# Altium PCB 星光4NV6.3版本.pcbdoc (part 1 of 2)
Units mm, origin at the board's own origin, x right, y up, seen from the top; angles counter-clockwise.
Board outline 96.4 x 47 mm, 2 copper layers (Top Layer, Bottom Layer), stack 1.58 mm thick; 27 components, 21 nets, 136 pads, 174 vias.
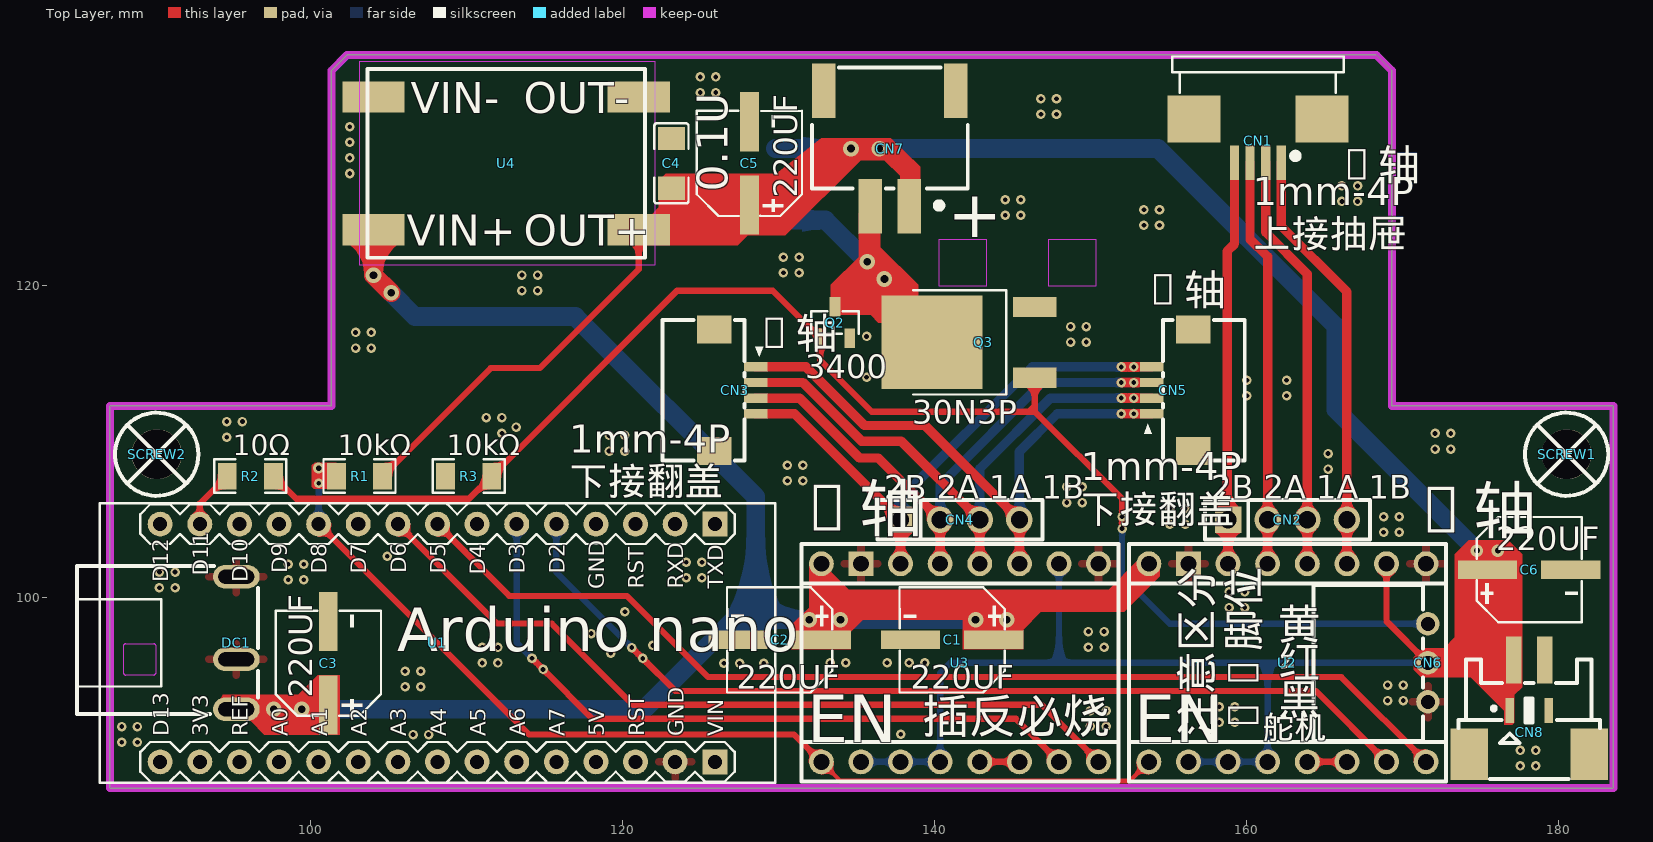
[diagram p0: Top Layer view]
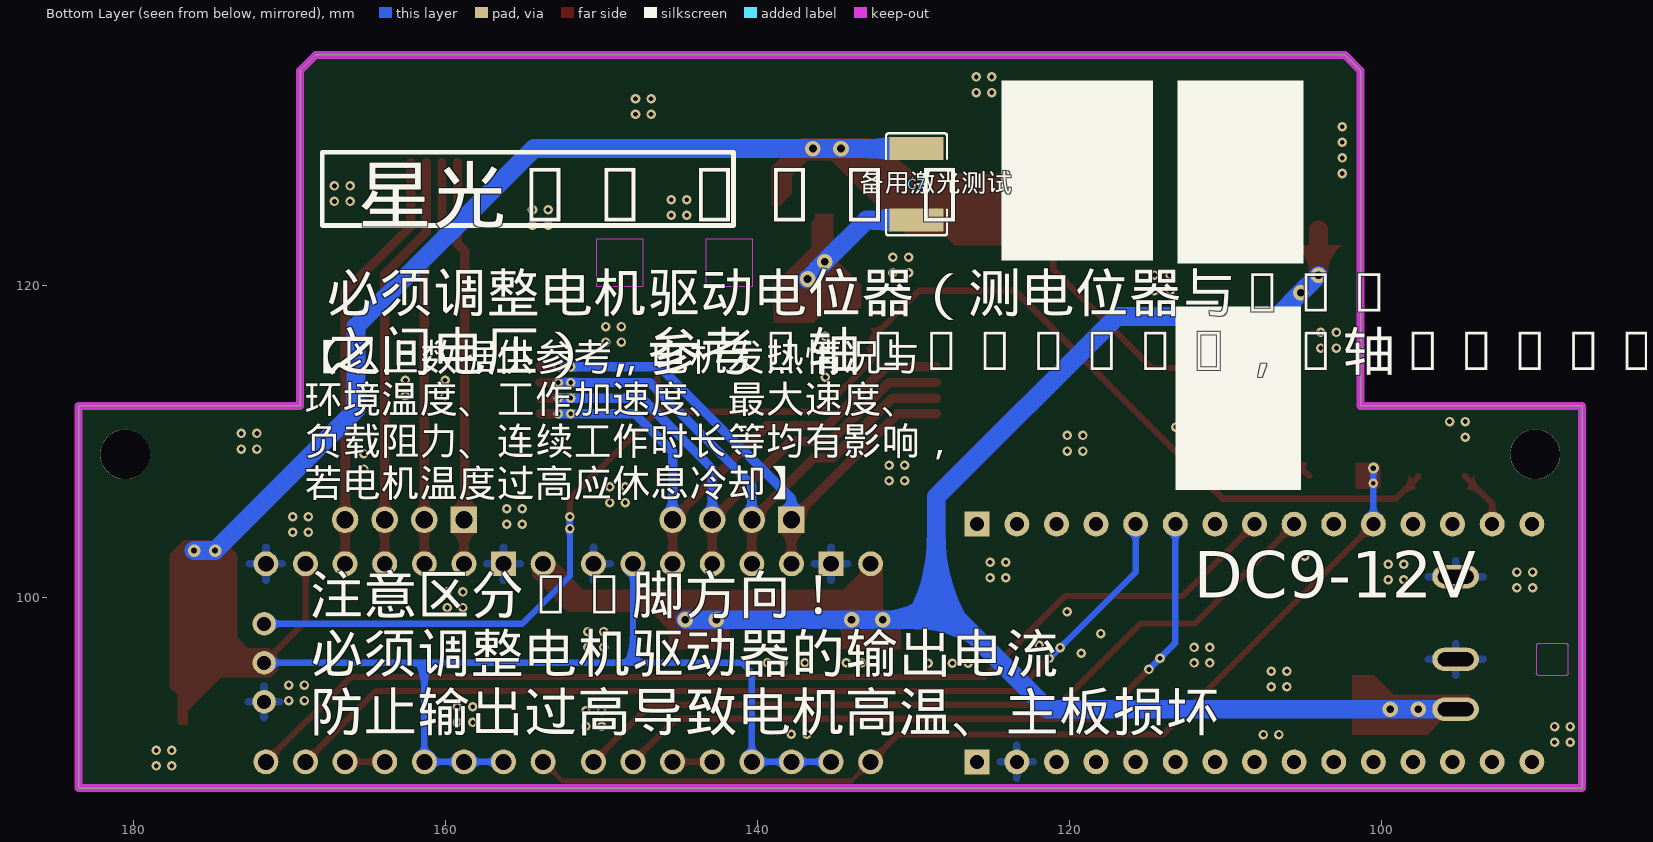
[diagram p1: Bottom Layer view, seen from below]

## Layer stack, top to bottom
Top Solder Mask Layer: solder mask 0.01, Dk 3.3
Top Layer: signal copper 0.035
Dielectric1: surface 1.51, FR4, Dk 4.5
Bottom Layer: signal copper 0.035
Bottom Solder Mask Layer: solder mask 0.01, Dk 3.3

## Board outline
102.322,134.757 168.322,134.757 169.322,133.757 169.322,112.257 169.322,119.257 169.322,112.257 183.522,112.257 183.522,87.757 87.122,87.757 87.122,112.257 101.322,112.257 101.322,133.757

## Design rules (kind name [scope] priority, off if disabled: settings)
BoardOutlineClearance copperThickness1oz [All] p0: genericclearance=0.254 ignorepadtopadclearanceinfootprint=FALSE except(0: Arc-SplitContinuation Track-SplitContinuation SMDPad-SplitContinuation THPad-SplitContinuation Via-SplitContinuation Fill-SplitContinuation Poly-SplitContinuation Region-SplitContinuation Text-SplitContinuation)
BoardOutlineClearance copperThickness2oz [All] p0: genericclearance=0.254 ignorepadtopadclearanceinfootprint=FALSE except(0: Arc-SplitContinuation Track-SplitContinuation SMDPad-SplitContinuation THPad-SplitContinuation Via-SplitContinuation Fill-SplitContinuation Poly-SplitContinuation Region-SplitContinuation Text-SplitContinuation)
BoardOutlineClearance Plane_innerPlane [All] p0: genericclearance=0.254 ignorepadtopadclearanceinfootprint=FALSE except(0: Arc-SplitContinuation Track-SplitContinuation SMDPad-SplitContinuation THPad-SplitContinuation Via-SplitContinuation Fill-SplitContinuation Poly-SplitContinuation Region-SplitContinuation Text-SplitContinuation)
BoardOutlineClearance Copper_copperRegion [All] p0: genericclearance=0.254 ignorepadtopadclearanceinfootprint=FALSE except(0: Arc-SplitContinuation Track-SplitContinuation SMDPad-SplitContinuation THPad-SplitContinuation Via-SplitContinuation Fill-SplitContinuation Poly-SplitContinuation Region-SplitContinuation Text-SplitContinuation)
BoardOutlineClearance Copper_copperRegion1 [All] p0: genericclearance=0.254 ignorepadtopadclearanceinfootprint=FALSE except(0: Arc-SplitContinuation Track-SplitContinuation SMDPad-SplitContinuation THPad-SplitContinuation Via-SplitContinuation Fill-SplitContinuation Poly-SplitContinuation Region-SplitContinuation Text-SplitContinuation)
BoardOutlineClearance otherClearance [All] p0: genericclearance=0.254 ignorepadtopadclearanceinfootprint=FALSE except(0: Arc-SplitContinuation Track-SplitContinuation SMDPad-SplitContinuation THPad-SplitContinuation Via-SplitContinuation Fill-SplitContinuation Poly-SplitContinuation Region-SplitContinuation Text-SplitContinuation)
Clearance copperThickness1oz [All] p1: gap=0.178 ignorepadtopadclearanceinfootprint=FALSE
Clearance copperThickness2oz [All] p1: gap=0.178 ignorepadtopadclearanceinfootprint=FALSE
Clearance Plane_innerPlane [All] p1: gap=0.178 ignorepadtopadclearanceinfootprint=FALSE
Clearance Copper_copperRegion [All] p1: gap=0.178 ignorepadtopadclearanceinfootprint=FALSE
Clearance Copper_copperRegion1 [All] p1: gap=0.178 ignorepadtopadclearanceinfootprint=FALSE
Clearance otherClearance [All] p1: gap=0.178 ignorepadtopadclearanceinfootprint=FALSE
DiffPairsRouting differentialPair [All] p1: maxuncoupledlength=10 minlimit=5.9843 maxlimit=Infinity mostfreqgap=5.9843 toplayer_minwidth=5 toplayer_prefwidth=10 toplayer_maxwidth=100 bottomlayer_minwidth=5 bottomlayer_prefwidth=10 bottomlayer_maxwidth=100
PasteMaskExpansion pasteMaskExpansion [All] p1: expansion=0
PlaneConnect innerPlane [All] p1: planeconnectstyle=Relief reliefexpansion=0.508 reliefentries=4 reliefconductorwidth=0.254 reliefairgap=0.254
PolygonConnect copperRegion [All] p1: connectstyle=Relief reliefentries=4 reliefconductorwidth=10 polygonreliefangle="90 Angle" airgapwidth=10
PolygonConnect copperRegion1 [All] p1: connectstyle=Relief reliefentries=4 reliefconductorwidth=19.685 polygonreliefangle="90 Angle" airgapwidth=10
RoutingVias viaSize [All] p1: viastyle="Through Hole" holewidth=12.0078 minholewidth=11.811 maxholewidth=248.0314 width=12.0078 minwidth=11.811 maxwidth=248.0314
SolderMaskExpansion solderMaskExpansion [All] p1: useseparateexpansions=TRUE expansion=2.0079 expansionbottom=2.0079
Width copperThickness1oz [All] p1: maxlimit=100 minlimit=5 preferedwidth=20
Width copperThickness2oz [All] p1: maxlimit=100 minlimit=5 preferedwidth=10

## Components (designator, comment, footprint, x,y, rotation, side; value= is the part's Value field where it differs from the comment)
C1 "" CAP-SMD_BD6.3-L6.6-W6.6-FD-1 141.122,97.257 r180 top
C2 "" CAP-SMD_BD6.3-L6.6-W6.6-FD-1 130.062,97.257 r180 top
C3 "" CAP-SMD_BD6.3-L6.6-W6.6-FD-1 101.122,95.757 r90 top
C4 "100nF" C1206 123.122,127.807 r270 top
C5 "" CAP-SMD_BD6.3-L6.6-W6.6-FD-1 128.122,127.807 r90 top
C6 "" CAP-SMD_BD6.3-L6.6-W6.6-FD-1 178.122,101.757 r0 top
C7 "" C1812 129.794,126.464 r90 bottom
CN1 "" FPC-SMD_4P-P1.00_AFA07-S04ECC-00 160.722,129.257 r180 top
CN2 "" HDR-TH_4P-P2.54-V-F 162.622,104.957 r0 top
CN3 "" FPC-SMD_4P-P1.00_10A20L04P 127.122,113.257 r270 top
CN4 "" HDR-TH_4P-P2.54-V-F 141.622,104.957 r0 top
CN5 "" FPC-SMD_4P-P1.00_10A20L04P 155.322,113.257 r90 top
CN6 "" HDR-TH_3P-P2.50_ZX-XH2.54-3PWZ 171.622,95.787 r270 top
CN7 "" CONN-SMD_2P-P2.54_MEGASTAR_ZX-XH2.54-2PWT 137.122,128.757 r180 top
CN8 "" CONN-SMD_1.25-3P 178.122,91.257 r0 top
DC1 "" DC-IN-TH_DC044 95.222,97.057 r0 top
Q2 "" SOT-23-3_L2.9-W1.3-P1.90-LS2.4-BR 133.604,117.602 r270 top
Q3 "" TO-252-2_L6.6-W6.1-P4.57-LS9.9-TL-CW 143.122,116.332 r180 top
R1 "10kΩ" R1206 103.122,107.757 r0 top
R2 "10Ω" R1206 96.122,107.757 r180 top
R3 "10kΩ" R1206 110.122,107.757 r0 top
SCREW1 "" M3螺丝 180.522,109.157 r0 top
SCREW2 "" M3螺丝 90.122,109.157 r0 top
U1 "" COMM-TH_ARDUINO_NANO 108.122,97.057 r0 top
U2 "" DIP-16_L20.3-W15.2-P2.54_LS12.7_A4988 162.622,95.787 r90 top
U3 "" DIP-16_L20.3-W15.2-P2.54_LS12.7_A4988 141.622,95.787 r90 top
U4 "" 迷你稳压模块 103.622,121.757 r0 top

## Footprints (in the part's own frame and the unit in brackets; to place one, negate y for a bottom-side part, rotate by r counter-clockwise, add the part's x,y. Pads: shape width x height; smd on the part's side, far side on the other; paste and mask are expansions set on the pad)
C1206 [mm]
  rect 1.485x1.728 smd: 1(-1.593,0) 2(1.593,0)
  silkscreen extent -2.56,-1.09 2.56,1.09
C1812 [mm]
  rect 1.485x3.456 smd: 1(-2.293,0) 2(2.293,0)
  silkscreen extent -3.26,-1.96 3.26,1.96
CAP-SMD_BD6.3-L6.6-W6.6-FD-1 [mm]
  rect 3.8x1.2 smd: 1(-2.67,0) 2(2.67,0)
  silkscreen extent -3.38,-3.38 3.38,3.38
COMM-TH_ARDUINO_NANO [mm]
  rect 1.6x1.6 hole 0.9: 1(17.78,7.62) 30(17.78,-7.62)
  round 1.6 hole 0.9: 2(15.24,7.62) 4(10.16,7.62) 6(5.08,7.62) 8(0,7.62) 10(-5.08,7.62) 12(-10.16,7.62) 14(-15.24,7.62) 15(-17.78,7.62) 16(-17.78,-7.62) 18(-12.7,-7.62) 20(-7.62,-7.62) 22(-2.54,-7.62) 24(2.54,-7.62) 26(7.62,-7.62) 28(12.7,-7.62) 29(15.24,-7.62)
  round 1.6 hole 0.9 copper offset 0,0: 3(12.7,7.62)
  round 1.6 hole 0.9 copper offset -0.001,0: 5(7.621,7.62) 7(2.541,7.62) 9(-2.539,7.62) 11(-7.619,7.62) 13(-12.699,7.62)
  round 1.6 hole 0.9 copper offset 0.001,0: 17(-15.241,-7.62) 19(-10.161,-7.62) 21(-5.081,-7.62) 23(-0.001,-7.62) 25(5.079,-7.62) 27(10.159,-7.62)
  silkscreen extent -23.11,-8.97 21.67,8.97
CONN-SMD_1.25-3P [mm]
  rect 0.52x1.6 smd: 1(-1.25,1.475) 3(1.25,1.475)
  rect 2.4x3.3 smd: 4(3.85,-1.325) 5(-3.85,-1.325)
  silkscreen extent -4.52,-2.92 4.53,2.24
CONN-SMD_2P-P2.54_MEGASTAR_ZX-XH2.54-2PWT [mm]
  rect 1.5x3.5 smd: 1(-1.25,3.7) 2(1.25,3.7) 3(-4.23,-3.7) 4(4.23,-3.7)
  silkscreen extent -5,-5.21 5,3.85
DC-IN-TH_DC044 [mm]
  oval 3x1.5 hole 0.9 slot 2.3 at 0 deg: 2(0,4.25) 3(0,-1.05) 4(0,-4.25)
  Board Outline Layer lines w0.003: -7.209,-1.939 -7.209,-0.161 cw(c-7.082,-0.161) -7.082,-0.034 -5.304,-0.034 cw(c-5.304,-0.161) -5.177,-0.161 -5.177,-1.939 cw(c-5.304,-1.939) -5.304,-2.066 -7.082,-2.066 cw(c-7.082,-1.939) -7.209,-1.939
  Board Outline Layer region: -7.209,-1.939 -7.209,-0.161 -7.199,-0.112 -7.172,-0.071 -7.131,-0.044 -7.082,-0.034 -7.082,-0.034 -5.304,-0.034 -5.255,-0.044 -5.214,-0.071 -5.187,-0.112 -5.177,-0.161 -5.177,-0.161 -5.177,-1.939 -5.187,-1.988 -5.214,-2.029 -5.255,-2.056 -5.304,-2.066 -5.304,-2.066 -7.082,-2.066 -7.131,-2.056 -7.172,-2.029 -7.199,-1.988 -7.209,-1.939
  Board Outline Layer region: -7.209,-1.939 -7.209,-0.161 -7.199,-0.112 -7.172,-0.071 -7.131,-0.044 -7.082,-0.034 -7.082,-0.034 -5.304,-0.034 -5.255,-0.044 -5.214,-0.071 -5.187,-0.112 -5.177,-0.161 -5.177,-0.161 -5.177,-1.939 -5.187,-1.988 -5.214,-2.029 -5.255,-2.056 -5.304,-2.066 -5.304,-2.066 -7.082,-2.066 -7.131,-2.056 -7.172,-2.029 -7.199,-1.988 -7.209,-1.939
  silkscreen extent -10.2,-4.55 1.4,4.95
DIP-16_L20.3-W15.2-P2.54_LS12.7_A4988 [mm]
  round 1.6 hole 1.02: 1(-6.35,8.89) 2(-6.35,6.35) 3(-6.35,3.81) 4(-6.35,1.27) 5(-6.35,-1.27) 6(-6.35,-3.81) 7(-6.35,-6.35) 8(-6.35,-8.89) 9(6.35,-8.89) 10(6.35,-6.35) 11(6.35,-3.81) 12(6.35,-1.27) 13(6.35,1.27) 14(6.35,3.81) 16(6.35,8.89)
  rect 1.6x1.6 hole 1.02: 15(6.35,6.35)
  silkscreen extent -7.62,-10.16 7.62,10.16
FPC-SMD_4P-P1.00_10A20L04P [mm]
  rect 0.6x1.5 smd: 1(-1.5,1.4) 2(-0.5,1.4) 3(0.5,1.4) 4(1.5,1.4)
  rect 1.8x2.2 smd: 5(3.9,-1.263) 6(-3.9,-1.263)
  silkscreen extent -4.5,-4.56 4.5,1.9
FPC-SMD_4P-P1.00_AFA07-S04ECC-00 [mm]
  rect 0.6x2.2 smd: 1(-1.5,1.4) 2(-0.5,1.4) 3(0.5,1.4) 4(1.5,1.4)
  rect 3.4x3 smd: 5(4.1,-1.4) 6(-4.1,-1.4)
  silkscreen extent -5.5,-5.4 5.5,1.17
HDR-TH_3P-P2.50_ZX-XH2.54-3PWZ [mm]
  round 1.5 hole 0.9: 1(-2.5,0) 2(0,0) 3(2.5,0)
  silkscreen extent -5,-7.32 5,-0.32
HDR-TH_4P-P2.54-V-F [mm]
  rect 1.7x1.7 hole 1.1: 1(-3.81,0)
  round 1.7 hole 1.1: 2(-1.27,0) 3(1.27,0) 4(3.81,0)
  silkscreen extent -5.29,-1.27 5.29,1.27
M3螺丝 [mil]
  round 126 hole 126: 1(0,0)
  silkscreen extent -105,-105 105,105
R1206 [mm]
  rect 1.208x1.701 smd: 1(-1.479,0) 2(1.479,0)
  silkscreen extent -2.31,-1.08 2.31,1.08
SOT-23-3_L2.9-W1.3-P1.90-LS2.4-BR [mm]
  rect 1.25x0.7 smd: 1(1,-0.95) 2(1,0.95) 3(-1,0)
  silkscreen extent -0.73,-1.53 0.73,1.53
TO-252-2_L6.6-W6.1-P4.57-LS9.9-TL-CW [mm]
  rect 2.8x1.3 smd: 1(-3.292,2.273) 3(-3.292,-2.273)
  rect 6.5x6 smd: 2(3.292,0)
  silkscreen extent -1.46,-3.35 4.51,3.34
迷你稳压模块 [mm]
  rect 4x2 smd: 1(0.4,10.3) 2(0.4,1.8) 3(17.4,10.3) 4(17.4,1.8)
  silkscreen extent 0,0 17.8,12.1

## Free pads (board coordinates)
  rect 1x3 smd: 1(177.122,95.957) 1(179.122,95.957)

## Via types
v1: diameter 0.61, hole 0.305, Top Layer to Bottom Layer, 159 vias
v2: diameter 1, hole 0.5, Top Layer to Bottom Layer, 12 vias
v3: diameter 0.8, hole 0.4, Top Layer to Bottom Layer, 2 vias
v4: diameter 0.7, hole 0.35, Top Layer to Bottom Layer, 1 vias

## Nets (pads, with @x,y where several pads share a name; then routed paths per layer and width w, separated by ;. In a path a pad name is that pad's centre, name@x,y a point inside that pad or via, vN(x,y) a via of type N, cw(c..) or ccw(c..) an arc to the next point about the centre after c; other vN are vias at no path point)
5V: C4.2 C5.1 C6.1 C7.2 CN6.2 CN7.1 CN8.1 pad.1@177.122,95.957 R1.2 U2.2 U2.3 U2.4 U2.10 U3.2 U3.3 U3.4 U3.10 U4.4 | length 153.5
  Top Layer w0.4: R1.2@104.601,107.757 111.525,114.681 114.681,114.681 121.022,121.022 U4.4@121.022,123.557 ; U2.10@168.972,102.137 168.972,98.437 CN6.2@171.622,95.787
  Bottom Layer w0.4: U3.2@135.272,89.437 U3.3@137.812,89.437 U3.4@140.352,89.437 140.352,95.14 140.999,95.787 147.585,95.787 ; U3.10@147.972,102.137 147.972,96.174 ; U2.2@156.272,89.437 U2.3@158.812,89.437 U2.4@161.352,89.437 161.352,95.411 ; CN6.2@171.622,95.787 161.728,95.787 ; 147.585,95.787 147.972,96.174 ; 147.585,95.787 148.359,95.787 ; 147.972,96.174 148.359,95.787 ; 148.359,95.787 160.976,95.787 ; 160.976,95.787 161.352,95.411 ; 160.976,95.787 161.728,95.787 ; 161.352,95.411 161.728,95.787
  Bottom Layer w1.2: C7.2@129.794,128.757 v2(134.635,128.757) v2(136.438,128.757) 154.326,128.757 165.735,117.348 165.735,112.014 v3(174.765,102.984) v3(176.115,102.984)
12V: C1.1 C2.1 C3.1 DC1.4 U2.16 U3.16 U4.2 | length 97.1
  Top Layer w1.2: U4.2@104.022,123.557 v2(104.022,120.641) v2(105.156,119.507)
  Bottom Layer w1.2: DC1.4@95.222,92.807 v2(97.622,92.807) v2(99.425,92.807) 121.382,92.807 127.127,98.552 ; v2(104.022,120.641) v2(105.156,119.507) 106.68,117.983 116.967,117.983 128.524,106.426 128.524,99.949 ; v2(144.622,98.552) v2(142.622,98.552) v2(133.953,98.552) v2(131.953,98.552) 129.921,98.552 ; 127.127,98.552 128.524,99.949 ; 127.127,98.552 129.921,98.552 ; 128.524,99.949 129.921,98.552
$1N38281: U3.5 U3.6 | length 2.5
  Top Layer w0.4: U3.5@142.892,89.437 U3.6@145.432,89.437
$1N38618: CN3.1 CN4.4 CN5.1 U3.11 | length 38.5
  Top Layer w0.6: CN3.1@128.522,114.757 131.75,114.757 135.505,111.002 139.387,111.002 CN4.4@145.432,104.957 U3.11@145.432,102.137 ; v1(151.967,111.757) v1(152.766,111.757) CN5.1@153.922,111.757
  Bottom Layer w0.6: CN4.4@145.432,104.957 145.432,109.326 147.863,111.757 v1(151.967,111.757) v1(152.766,111.757)
$1N38619: CN3.2 CN4.3 CN5.2 U3.12 | length 37.8
  Top Layer w0.6: CN3.2@128.522,113.757 131.552,113.757 135.308,110.001 137.848,110.001 CN4.3@142.892,104.957 U3.12@142.892,102.137 ; v1(151.967,112.757) v1(152.766,112.757) CN5.2@153.922,112.757
  Bottom Layer w0.6: CN4.3@142.892,104.957 142.892,108.221 147.428,112.757 v1(151.967,112.757) v1(152.766,112.757)
$1N38620: CN3.3 CN4.2 CN5.3 U3.13 | length 37.2
  Top Layer w0.6: CN3.3@128.522,112.757 131.337,112.757 135.174,108.92 136.389,108.92 CN4.2@140.352,104.957 U3.13@140.352,102.137 ; v1(151.967,113.757) v1(152.766,113.757) CN5.3@153.922,113.757
  Bottom Layer w0.6: CN4.2@140.352,104.957 140.352,107.205 146.904,113.757 v1(151.967,113.757) v1(152.766,113.757)
$1N38622: CN3.4 CN4.1 CN5.4 U3.14 | length 36.7
  Top Layer w0.6: CN3.4@128.522,111.757 131.012,111.757 CN4.1@137.812,104.957 U3.14@137.812,102.137 ; v1(151.967,114.757) v1(152.766,114.757) CN5.4@153.922,114.757
  Bottom Layer w0.6: CN4.1@137.812,104.957 137.812,106.316 146.253,114.757 v1(151.967,114.757) v1(152.766,114.757)
$1N39292: U2.5 U2.6 | length 2.5
  Top Layer w0.4: U2.5@163.892,89.437 U2.6@166.432,89.437
$1N39467: CN1.1 CN2.4 U2.11 | length 27.5
  Top Layer w0.6: CN1.1@162.222,127.857 162.222,123.782 166.432,119.572 CN2.4@166.432,104.957 U2.11@166.432,102.137
$1N39468: CN1.2 CN2.3 U2.12 | length 26.8
  Top Layer w0.6: CN1.2@161.222,127.857 161.222,123.385 163.892,120.715 CN2.3@163.892,104.957 U2.12@163.892,102.137
$1N39469: CN1.4 CN2.1 U2.14 | length 25.9
  Top Layer w0.6: U2.14@158.812,102.137 CN2.1@158.812,104.957 158.75,105.019 158.75,122.174 159.222,122.646 CN1.4@159.222,127.857
$1N39470: CN1.3 CN2.2 U2.13 | length 26.2
  Top Layer w0.6: CN1.3@160.222,127.857 160.222,122.947 161.352,121.817 CN2.2@161.352,104.957 U2.13@161.352,102.137
$1N40367: C7.1 CN7.2 Q2.3 Q3.2 | length 8.5
  Bottom Layer w1.2: C7.1@129.794,124.172 133.003,124.172 v2(135.681,121.494) v2(136.779,120.396)
$1N40669: CN6.1 Q2.1 Q3.1 R2.1 R3.2 | length 96.2
  Top Layer w0.4: R2.1@97.601,107.757 99.059,106.299 110.143,106.299 R3.2@111.601,107.757 123.478,119.634 129.622,119.634 Q2.1@132.654,116.602 132.654,115.195 135.962,111.887 146.037,111.887 ; Q3.1@146.414,114.059 146.414,112.264 ; v1(152.019,104.394) v1(152.019,105.148) 152.019,106.299 146.431,111.887 ; 146.037,111.887 146.414,112.264 ; 146.037,111.887 146.431,111.887 ; 146.414,112.264 146.414,111.904 146.431,111.887
  Bottom Layer w0.4: v1(152.019,105.148) v1(152.019,104.394) 152.019,101.346 155.078,98.287 CN6.1@171.622,98.287
D2/X-STEP: U1.5 U2.7 | length 62.3
  Top Layer w0.4: v1(120.58,96.763) v1(121.281,96.063) 123.364,93.98 164.429,93.98 U2.7@168.972,89.437
  Bottom Layer w0.4: U1.5@115.743,104.677 115.742,101.602 v1(120.58,96.763) v1(121.281,96.063)
D3/Y-STEP: U1.6 U3.7 | length 46.6
  Top Layer w0.4: v1(114.182,96.077) v1(114.895,95.364) 118.057,92.202 145.207,92.202 U3.7@147.972,89.437
  Bottom Layer w0.4: U1.6@113.202,104.677 113.202,97.057 v1(114.182,96.077) v1(114.895,95.364)
D5/X-DIR: U1.8 U2.8 | length 69.7
  Top Layer w0.4: U1.8@108.122,104.677 112.723,100.076 120.269,100.076 125.476,94.869 166.08,94.869 U2.8@171.512,89.437
D6/Y-DIR: U1.9 U3.8 | length 51.2
  Top Layer w0.4: U1.9@105.583,104.677 111.961,98.298 115.443,98.298 120.65,93.091 146.858,93.091 U3.8@150.512,89.437
D8/EN: R1.1 U1.11 U2.1 U3.1 | length 64.1
  Top Layer w0.3: U3.1@132.732,89.437 133.962,88.207 152.502,88.207 U2.1@153.732,89.437
  Top Layer w0.4: U1.11@100.503,104.677 113.993,91.186 130.983,91.186 U3.1@132.732,89.437
  Bottom Layer w0.4: U1.11@100.503,104.677 v1(100.502,107.303) v4(100.502,108.265)
D11/PWM: R2.2 U1.14 | length 3.8
  Top Layer w0.4: U1.14@92.882,104.677 92.882,105.996 R2.2@94.643,107.757
GND: C1.2 C2.2 C3.2 C4.1 C5.2 C6.2 CN1.5 CN1.6 CN3.5 CN3.6 CN5.5 CN5.6 CN6.3 CN7.3 CN7.4 CN8.3 CN8.4 CN8.5 DC1.2 DC1.3 pad.1@179.122,95.957 Q2.2 Q3.3 R3.1 U1.29 U2.9 U2.15 U3.9 U3.15 U4.1 U4.3
  other v1: 177.546,89.17 178.546,89.17 177.546,90.17 178.546,90.17 87.884,90.694 88.884,90.694 106.553,91.186 107.553,91.186 136.822,91.202 137.822,91.202 87.884,91.694 88.884,91.694 149.987,91.71 150.987,91.71 158.242,91.964 159.242,91.964 149.987,92.71 150.987,92.71 158.242,92.964 159.242,92.964 169.037,93.361 170.037,93.361 106.045,94.25 107.045,94.25 169.037,94.361 170.037,94.361 106.045,95.25 107.045,95.25 126.492,95.758 127.492,95.758 129.045,95.758 110.998,95.774 111.998,95.774 133.293,95.787 134.293,95.787 136.949,95.787 138.361,95.787 139.361,95.787 119.237,96.393 110.998,96.774 111.998,96.774 149.86,96.79 150.86,96.79 121.92,96.901 117.983,97.663 149.86,97.79 150.86,97.79 120.142,99.06 158.877,99.33 159.877,99.33 158.877,100.33 159.877,100.33 90.297,100.6 91.297,100.6 98.552,101.108 99.552,101.108 124.079,101.235 125.079,101.235 90.297,101.6 91.297,101.6 98.552,102.108 99.552,102.108 124.079,102.235 125.079,102.235 104.902,102.616 168.783,104.156 169.783,104.156 155.067,104.664 156.067,104.664 168.783,105.156 169.783,105.156 155.067,105.664 156.067,105.664 148.463,106.061 149.463,106.061 148.463,107.061 149.463,107.061 130.556,107.458 131.556,107.458 165.227,108.204 130.556,108.458 131.556,108.458 165.227,109.204 119.126,109.363 120.126,109.363 172.085,109.49 173.085,109.49 94.615,110.252 119.126,110.363 120.126,110.363 172.085,110.49 173.085,110.49 112.252,110.506 113.157,110.901 94.615,111.252 95.615,111.252 111.252,111.506 112.252,111.506 160.02,112.903 162.56,112.903 160.02,113.903 162.56,113.903 135.636,114.092 102.87,115.967 103.87,115.967 148.717,116.348 149.717,116.348 135.636,116.713 102.87,116.967 103.87,116.967 148.717,117.348 149.717,117.348 113.538,119.65 114.538,119.65 113.538,120.65 114.538,120.65 130.302,120.793 131.302,120.793 130.302,121.793 131.302,121.793 153.416,123.841 154.416,123.841 144.526,124.476 145.526,124.476 153.416,124.841 154.416,124.841 166.116,125.365 167.116,125.365 144.526,125.476 145.526,125.476 166.116,126.365 167.116,126.365 102.489,127.159 102.489,128.159 102.489,129.159 102.489,130.159 146.812,130.953 147.812,130.953 146.812,131.953 147.812,131.953 124.968,132.35 125.968,132.35 124.968,133.35 125.968,133.35
pads on no net: SCREW1.1 SCREW2.1 U1.1 U1.2 U1.3 U1.4 U1.7 U1.10 U1.12 U1.13 U1.15 U1.16 U1.17 U1.18 U1.19 U1.20 U1.21 U1.22 U1.23 U1.24 U1.25 U1.26 U1.27 U1.28 U1.30

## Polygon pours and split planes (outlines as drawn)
GND on Top Layer (solid, remove dead copper, pour order 0): 81.026,139.065 191.262,139.065 191.262,82.296 81.026,82.296
GND on Bottom Layer (solid, remove dead copper, pour order 2): 76.2,141.986 197.866,141.986 197.866,76.2 76.2,76.2

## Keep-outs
Top Layer:
  region: 103.124,134.366 122.047,134.366 122.047,121.285 103.124,121.285
Board Outline Layer:
  region: 140.296,122.936 143.296,122.936 143.296,119.936 140.296,119.936
  region: 140.296,122.936 143.296,122.936 143.296,119.936 140.296,119.936
  region: 147.322,122.936 150.322,122.936 150.322,119.936 147.322,119.936
  region: 147.322,122.936 150.322,122.936 150.322,119.936 147.322,119.936
  lines w0.003: 140.296,119.936 143.296,119.936 143.296,122.936 140.296,122.936 140.296,119.936 ; 147.322,119.936 150.322,119.936 150.322,122.936 147.322,122.936 147.322,119.936
  lines w0.5: 169.322,112.257 169.322,133.757 168.322,134.757 102.322,134.757 101.322,133.757 101.322,112.257 87.122,112.257 87.122,87.757 183.522,87.757 183.522,112.257 169.322,112.257 ; 169.322,112.257 169.322,119.257 169.322,112.257

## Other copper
Top Layer:
  region net 5V: 170.727,96.139 171.302,96.714 172.66,96.714 173.355,97.409 173.355,102.743 174.244,103.632 176.784,103.632 177.673,102.743 177.673,94.234 177.165,93.726 177.165,91.948 177.038,91.821 176.53,91.821 176.53,92.71 174.371,94.869 171.196,94.869 170.727,95.338
  region net 12V: 131.953,102.108 131.953,99.327 130.81,98.184 130.81,96.647 134.62,96.647 134.62,97.79 135.382,98.552 141.805,98.552 141.805,96.647 145.669,96.647 145.669,97.917 146.812,99.06 152.146,99.06 154.432,101.346 154.432,102.342 152.985,102.342 151.157,100.457 134.493,100.457 132.842,102.108
  region net 12V: 94.234,93.472 94.362,93.726 99.187,93.726 100.457,94.996 101.854,94.996 101.854,91.186 97.028,91.186 96.139,92.075 94.488,92.075 94.234,92.329
  region net 5V: 120.186,124.46 121.793,124.46 122.322,124.989 122.322,126.707 122.742,127.127 129.852,127.127 132.723,129.413 137.187,129.413 139.065,127.583 139.065,125.095 138.811,124.841 137.795,125.857 137.795,127 136.779,128.016 135.255,128.016 130.429,123.19 128.016,123.19 127.381,122.555 121.031,122.555 121.031,123.615
  region net $1N40367: 135.128,124.587 135.128,121.793 133.35,120.015 133.35,118.618 133.858,118.11 135.89,118.11 136.398,117.602 138.938,117.602 138.938,120.015 136.525,122.428 136.525,124.079 136.271,124.333 136.271,124.587
  region net D8/EN: 101.643,108.607 100.237,108.607 100.076,108.446 100.076,107.061 100.203,106.934 101.643,106.934
  region net D8/EN: 101.414,104.048 101.131,103.765 101.091,103.802 101.053,103.831 101.015,103.854 100.977,103.871 100.939,103.883 100.902,103.89 100.824,103.895 100.743,103.891 100.655,103.883 100.559,103.877 100.452,103.879 101.3,104.727 101.302,104.62 101.296,104.524 101.288,104.436 101.284,104.355 101.289,104.277 101.296,104.24 101.308,104.202 101.325,104.164 101.348,104.126 101.377,104.088
  region net D6/Y-DIR: 106.494,104.048 106.211,103.765 106.171,103.802 106.133,103.831 106.095,103.854 106.057,103.871 106.019,103.883 105.982,103.89 105.904,103.895 105.823,103.891 105.735,103.883 105.639,103.877 105.532,103.879 106.38,104.727 106.382,104.62 106.376,104.524 106.368,104.436 106.364,104.355 106.369,104.277 106.376,104.24 106.388,104.202 106.405,104.164 106.428,104.126 106.457,104.088
  region net D5/X-DIR: 109.034,104.048 108.751,103.765 108.711,103.802 108.673,103.831 108.635,103.854 108.597,103.871 108.559,103.883 108.522,103.89 108.444,103.895 108.363,103.891 108.275,103.883 108.179,103.877 108.072,103.879 108.92,104.727 108.922,104.62 108.916,104.524 108.908,104.436 108.904,104.355 108.909,104.277 108.916,104.24 108.928,104.202 108.945,104.164 108.968,104.126 108.997,104.088
  region net D11/PWM: 92.682,105.766 93.082,105.766 93.084,105.713 93.091,105.665 93.102,105.622 93.116,105.583 93.134,105.548 93.156,105.516 93.207,105.458 93.268,105.403 93.335,105.347 93.407,105.283 93.482,105.206 92.282,105.206 92.357,105.283 92.429,105.347 92.496,105.403 92.557,105.458 92.608,105.516 92.63,105.548 92.648,105.583 92.662,105.622 92.673,105.665 92.68,105.713
  region net D5/X-DIR: 170.6,90.066 170.883,90.349 170.923,90.312 170.961,90.283 170.999,90.26 171.037,90.243 171.075,90.231 171.112,90.224 171.19,90.219 171.271,90.223 171.359,90.231 171.455,90.237 171.562,90.235 170.714,89.387 170.712,89.494 170.718,89.59 170.726,89.678 170.73,89.759 170.725,89.837 170.718,89.874 170.706,89.912 170.689,89.95 170.666,89.988 170.637,90.026
  region net D2/X-STEP: 168.06,90.066 168.343,90.349 168.383,90.312 168.421,90.283 168.459,90.26 168.497,90.243 168.535,90.231 168.572,90.224 168.65,90.219 168.731,90.223 168.819,90.231 168.915,90.237 169.022,90.235 168.174,89.387 168.172,89.494 168.178,89.59 168.186,89.678 168.19,89.759 168.185,89.837 168.178,89.874 168.166,89.912 168.149,89.95 168.126,89.988 168.097,90.026
  region net $1N39292: 165.343,89.237 165.343,89.637 165.396,89.639 165.444,89.646 165.487,89.657 165.526,89.671 165.561,89.689 165.593,89.711 165.651,89.762 165.706,89.823 165.762,89.89 165.826,89.962 165.903,90.037 165.903,88.837 165.826,88.912 165.762,88.984 165.706,89.051 165.651,89.112 165.593,89.163 165.561,89.185 165.526,89.203 165.487,89.217 165.444,89.228 165.396,89.235
  region net $1N39292: 164.981,89.637 164.981,89.237 164.928,89.235 164.88,89.228 164.837,89.217 164.798,89.203 164.763,89.185 164.731,89.163 164.673,89.112 164.618,89.051 164.562,88.984 164.498,88.912 164.421,88.837 164.421,90.037 164.498,89.962 164.562,89.89 164.618,89.823 164.673,89.762 164.731,89.711 164.763,89.689 164.798,89.671 164.837,89.657 164.88,89.646 164.928,89.639
  region net D8/EN: 153.068,88.561 152.856,88.773 152.896,88.817 152.927,88.859 152.95,88.899 152.966,88.938 152.976,88.977 152.98,89.015 152.977,89.093 152.963,89.175 152.946,89.266 152.934,89.369 152.932,89.426 152.934,89.487 153.782,88.639 153.721,88.637 153.664,88.639 153.561,88.651 153.47,88.668 153.388,88.682 153.31,88.685 153.272,88.681 153.233,88.671 153.194,88.655 153.154,88.632 153.112,88.601
  region net 5V: 169.172,101.048 168.772,101.048 168.77,101.101 168.763,101.149 168.752,101.192 168.738,101.231 168.72,101.266 168.698,101.298 168.647,101.356 168.586,101.411 168.519,101.467 168.447,101.531 168.372,101.608 169.572,101.608 169.497,101.531 169.425,101.467 169.358,101.411 169.297,101.356 169.246,101.298 169.224,101.266 169.206,101.231 169.192,101.192 169.181,101.149 169.174,101.101
  region net $1N39467: 166.132,103.226 166.732,103.226 166.739,103.144 166.758,103.067 166.787,102.994 166.826,102.925 166.871,102.858 166.922,102.794 167.032,102.666 165.832,102.666 165.942,102.794 165.993,102.858 166.038,102.925 166.077,102.994 166.106,103.067 166.125,103.144
  region net $1N39468: 163.592,103.226 164.192,103.226 164.199,103.144 164.218,103.067 164.247,102.994 164.286,102.925 164.331,102.858 164.382,102.794 164.492,102.666 163.292,102.666 163.402,102.794 163.453,102.858 163.498,102.925 163.537,102.994 163.566,103.067 163.585,103.144
  region net $1N39470: 161.052,103.226 161.652,103.226 161.659,103.144 161.678,103.067 161.707,102.994 161.746,102.925 161.791,102.858 161.842,102.794 161.952,102.666 160.752,102.666 160.862,102.794 160.913,102.858 160.958,102.925 160.997,102.994 161.026,103.067 161.045,103.144
  region net $1N39469: 158.512,103.226 159.112,103.226 159.119,103.144 159.138,103.067 159.167,102.994 159.206,102.925 159.251,102.858 159.302,102.794 159.412,102.666 158.212,102.666 158.322,102.794 158.373,102.858 158.418,102.925 158.457,102.994 158.486,103.067 158.505,103.144
  region net D6/Y-DIR: 149.6,90.066 149.883,90.349 149.923,90.312 149.961,90.283 149.999,90.26 150.037,90.243 150.075,90.231 150.112,90.224 150.19,90.219 150.271,90.223 150.359,90.231 150.455,90.237 150.562,90.235 149.714,89.387 149.712,89.494 149.718,89.59 149.726,89.678 149.73,89.759 149.725,89.837 149.718,89.874 149.706,89.912 149.689,89.95 149.666,89.988 149.637,90.026
  region net D3/Y-STEP: 147.06,90.066 147.343,90.349 147.383,90.312 147.421,90.283 147.459,90.26 147.497,90.243 147.535,90.231 147.572,90.224 147.65,90.219 147.731,90.223 147.819,90.231 147.915,90.237 148.022,90.235 147.174,89.387 147.172,89.494 147.178,89.59 147.186,89.678 147.19,89.759 147.185,89.837 147.178,89.874 147.166,89.912 147.149,89.95 147.126,89.988 147.097,90.026
  region net $1N38281: 144.343,89.237 144.343,89.637 144.396,89.639 144.444,89.646 144.487,89.657 144.526,89.671 144.561,89.689 144.593,89.711 144.651,89.762 144.706,89.823 144.762,89.89 144.826,89.962 144.903,90.037 144.903,88.837 144.826,88.912 144.762,88.984 144.706,89.051 144.651,89.112 144.593,89.163 144.561,89.185 144.526,89.203 144.487,89.217 144.444,89.228 144.396,89.235
  region net $1N38281: 143.981,89.637 143.981,89.237 143.928,89.235 143.88,89.228 143.837,89.217 143.798,89.203 143.763,89.185 143.731,89.163 143.673,89.112 143.618,89.051 143.562,88.984 143.498,88.912 143.421,88.837 143.421,90.037 143.498,89.962 143.562,89.89 143.618,89.823 143.673,89.762 143.731,89.711 143.763,89.689 143.798,89.671 143.837,89.657 143.88,89.646 143.928,89.639
  region net D8/EN: 133.608,88.773 133.396,88.561 133.352,88.601 133.31,88.632 133.27,88.655 133.231,88.671 133.192,88.681 133.154,88.685 133.076,88.682 132.994,88.668 132.903,88.651 132.8,88.639 132.743,88.637 132.682,88.639 133.53,89.487 133.532,89.426 133.53,89.369 133.518,89.266 133.501,89.175 133.487,89.093 133.484,89.015 133.488,88.977 133.498,88.938 133.514,88.899 133.537,88.859 133.568,88.817
  region net D8/EN: 131.82,90.066 132.103,90.349 132.143,90.312 132.181,90.283 132.219,90.26 132.257,90.243 132.295,90.231 132.332,90.224 132.41,90.219 132.491,90.223 132.579,90.231 132.675,90.237 132.782,90.235 131.934,89.387 131.932,89.494 131.938,89.59 131.946,89.678 131.95,89.759 131.945,89.837 131.938,89.874 131.926,89.912 131.909,89.95 131.886,89.988 131.857,90.026
  region net $1N38618: 145.132,103.226 145.732,103.226 145.739,103.144 145.758,103.067 145.787,102.994 145.826,102.925 145.871,102.858 145.922,102.794 146.032,102.666 144.832,102.666 144.942,102.794 144.993,102.858 145.038,102.925 145.077,102.994 145.106,103.067 145.125,103.144
  region net $1N38619: 142.592,103.226 143.192,103.226 143.199,103.144 143.218,103.067 143.247,102.994 143.286,102.925 143.331,102.858 143.382,102.794 143.492,102.666 142.292,102.666 142.402,102.794 142.453,102.858 142.498,102.925 142.537,102.994 142.566,103.067 142.585,103.144
  region net $1N38620: 140.052,103.226 140.652,103.226 140.659,103.144 140.678,103.067 140.707,102.994 140.746,102.925 140.791,102.858 140.842,102.794 140.952,102.666 139.752,102.666 139.862,102.794 139.913,102.858 139.958,102.925 139.997,102.994 140.026,103.067 140.045,103.144
  region net $1N38622: 137.512,103.226 138.112,103.226 138.119,103.144 138.138,103.067 138.167,102.994 138.206,102.925 138.251,102.858 138.302,102.794 138.412,102.666 137.212,102.666 137.322,102.794 137.373,102.858 137.418,102.925 137.457,102.994 137.486,103.067 137.505,103.144
  region net 5V: 170.759,96.368 171.041,96.651 171.077,96.618 171.113,96.591 171.148,96.569 171.183,96.553 171.218,96.542 171.253,96.534 171.325,96.527 171.401,96.528 171.483,96.534 171.571,96.538 171.669,96.536 170.873,95.74 170.872,95.838 170.876,95.926 170.881,96.008 170.882,96.084 170.876,96.156 170.868,96.191 170.856,96.226 170.84,96.261 170.818,96.296 170.792,96.332
  region net $1N39469: 159.112,103.207 158.512,103.207 ccw(c157.387,103.207) 158.062,104.107 159.562,104.107 ccw(c160.237,103.207)
  region net $1N39469: 158.45,106.707 159.05,106.707 ccw(c160.175,106.707) 159.5,105.807 158,105.807 ccw(c157.325,106.707)
  region net $1N39470: 161.652,103.8 161.052,103.8 161.05,103.846 161.044,103.891 161.023,103.973 160.99,104.05 160.947,104.121 160.895,104.19 160.838,104.257 160.715,104.395 161.99,104.395 161.866,104.257 161.809,104.19 161.757,104.121 161.714,104.05 161.681,103.973 161.66,103.891 161.654,103.846
  region net $1N39470: 161.052,106.114 161.652,106.114 161.654,106.068 161.66,106.023 161.681,105.941 161.714,105.864 161.757,105.793 161.809,105.724 161.866,105.657 161.99,105.519 160.715,105.519 160.838,105.657 160.895,105.724 160.947,105.793 160.99,105.864 161.023,105.941 161.044,106.023 161.05,106.068
  region net $1N39468: 164.192,103.8 163.592,103.8 163.59,103.846 163.584,103.891 163.563,103.973 163.53,104.05 163.487,104.121 163.435,104.19 163.378,104.257 163.255,104.395 164.53,104.395 164.406,104.257 164.349,104.19 164.297,104.121 164.254,104.05 164.221,103.973 164.2,103.891 164.194,103.846
  region net $1N39468: 163.592,106.114 164.192,106.114 164.194,106.068 164.2,106.023 164.221,105.941 164.254,105.864 164.297,105.793 164.349,105.724 164.406,105.657 164.53,105.519 163.255,105.519 163.378,105.657 163.435,105.724 163.487,105.793 163.53,105.864 163.563,105.941 163.584,106.023 163.59,106.068
  region net $1N39467: 166.732,103.8 166.132,103.8 166.13,103.846 166.124,103.891 166.103,103.973 166.07,104.05 166.027,104.121 165.975,104.19 165.918,104.257 165.795,104.395 167.07,104.395 166.946,104.257 166.889,104.19 166.837,104.121 166.794,104.05 166.761,103.973 166.74,103.891 166.734,103.846
  region net $1N39467: 166.132,106.114 166.732,106.114 166.734,106.068 166.74,106.023 166.761,105.941 166.794,105.864 166.837,105.793 166.889,105.724 166.946,105.657 167.07,105.519 165.795,105.519 165.918,105.657 165.975,105.724 166.027,105.793 166.07,105.864 166.103,105.941 166.124,106.023 166.13,106.068
  region net $1N38622: 136.644,105.701 137.068,106.125 ccw(c138.023,107.398) 138.023,105.807 136.962,104.746 ccw(c135.371,104.746)
  region net $1N38622: 138.112,103.207 137.512,103.207 ccw(c136.387,103.207) 137.062,104.107 138.562,104.107 ccw(c139.237,103.207)
  region net $1N38620: 139.322,105.563 139.746,105.987 139.78,105.956 139.816,105.928 139.889,105.885 139.967,105.855 140.048,105.835 140.132,105.822 140.22,105.815 140.405,105.805 139.504,104.904 139.494,105.089 139.487,105.177 139.474,105.261 139.454,105.342 139.424,105.42 139.381,105.493 139.353,105.529
  region net $1N38620: 140.652,103.8 140.052,103.8 140.05,103.846 140.044,103.891 140.023,103.973 139.99,104.05 139.947,104.121 139.895,104.19 139.838,104.257 139.715,104.395 140.989,104.395 140.866,104.257 140.809,104.19 140.757,104.121 140.714,104.05 140.681,103.973 140.66,103.891 140.654,103.846
  region net $1N38619: 141.862,105.563 142.286,105.987 142.32,105.956 142.356,105.928 142.429,105.885 142.507,105.855 142.588,105.835 142.672,105.822 142.76,105.815 142.945,105.805 142.044,104.904 142.034,105.089 142.027,105.177 142.014,105.261 141.994,105.342 141.964,105.42 141.921,105.493 141.893,105.529
  region net $1N38619: 143.192,103.8 142.592,103.8 142.59,103.846 142.584,103.891 142.563,103.973 142.53,104.05 142.487,104.121 142.435,104.19 142.378,104.257 142.255,104.395 143.529,104.395 143.406,104.257 143.349,104.19 143.297,104.121 143.254,104.05 143.221,103.973 143.2,103.891 143.194,103.846
  region net $1N38618: 144.402,105.563 144.826,105.987 144.86,105.956 144.896,105.928 144.969,105.885 145.047,105.855 145.128,105.835 145.212,105.822 145.3,105.815 145.485,105.805 144.584,104.904 144.574,105.089 144.567,105.177 144.554,105.261 144.534,105.342 144.504,105.42 144.461,105.493 144.433,105.529
  region net $1N38618: 145.732,103.8 145.132,103.8 145.13,103.846 145.124,103.891 145.103,103.973 145.07,104.05 145.027,104.121 144.975,104.19 144.918,104.257 144.795,104.395 146.069,104.395 145.946,104.257 145.889,104.19 145.837,104.121 145.794,104.05 145.761,103.973 145.74,103.891 145.734,103.846
  region net $1N40669: 132.092,116.881 132.1,117.439 ccw(c132.736,118.288) 132.736,117.227 132.304,116.245 ccw(c131.243,116.245)
  region net $1N40669: 132.854,115.377 132.454,115.377 ccw(c131.179,115.377) 132.304,115.977 133.004,115.977 ccw(c134.129,115.377)
  region net 12V: 104.622,120.757 103.422,120.757 ccw(c101.172,120.757) 102.522,122.557 105.522,122.557 ccw(c106.872,120.757)
  region net 5V: 121.222,121.957 120.822,121.957 ccw(c120.072,121.957) 120.522,122.557 121.522,122.557 ccw(c121.972,121.957)
  region net $1N40669: 146.614,112.809 146.214,112.809 ccw(c145.464,112.809) 145.914,113.409 146.914,113.409 ccw(c147.364,112.809)
  region net D11/PWM: 93.863,106.694 93.827,107.224 ccw(c92.979,107.86) 94.039,107.86 94.5,106.906 ccw(c94.5,105.846)
  region net $1N40669: 98.417,107.224 98.381,106.694 ccw(c97.744,105.846) 97.744,106.906 98.205,107.86 ccw(c99.265,107.86)
  region net $1N40669: 110.821,106.694 110.785,107.224 ccw(c109.936,107.86) 110.997,107.86 111.457,106.906 ccw(c111.457,105.846)
  region net $1N40669: 112.381,108.82 112.417,108.29 ccw(c113.265,107.654) 112.205,107.654 111.744,108.608 ccw(c111.744,109.668)
  region net 5V: 105.381,108.82 105.417,108.29 ccw(c106.265,107.654) 105.205,107.654 104.744,108.608 ccw(c104.744,109.668)
  region net D2/X-STEP: 121.716,95.91 121.433,95.627 121.392,95.674 121.358,95.715 121.339,95.731 121.318,95.744 121.293,95.754 121.262,95.758 121.586,96.082 121.59,96.051 121.599,96.026 121.613,96.005 121.629,95.986 121.67,95.951
  region net D2/X-STEP: 120.846,96.215 121.129,96.498 121.17,96.451 121.205,96.41 121.223,96.394 121.244,96.381 121.27,96.372 121.3,96.367 120.977,96.043 120.972,96.074 120.963,96.099 120.95,96.12 120.933,96.139 120.893,96.174
  region net $1N38622: 152.4,114.457 152.4,115.057 152.766,115.062 152.766,114.452
  region net $1N38622: 153.132,115.057 153.132,114.457 152.766,114.452 152.766,115.062
  region net $1N38622: 152.333,115.057 152.333,114.457 151.967,114.452 151.967,115.062
  region net $1N38620: 152.333,114.057 152.333,113.457 151.967,113.452 151.967,114.062
  region net $1N38620: 153.132,114.057 153.132,113.457 152.766,113.452 152.766,114.062
  region net $1N38620: 152.4,113.457 152.4,114.057 152.766,114.062 152.766,113.452
  region net $1N38619: 152.333,113.057 152.333,112.457 151.967,112.452 151.967,113.062
  region net $1N38619: 153.132,113.057 153.132,112.457 152.766,112.452 152.766,113.062
  region net $1N38619: 152.4,112.457 152.4,113.057 152.766,113.062 152.766,112.452
  region net $1N38618: 152.333,112.057 152.333,111.457 151.967,111.452 151.967,112.062
  region net $1N38618: 152.4,111.457 152.4,112.057 152.766,112.062 152.766,111.452
  region net $1N38618: 153.132,112.057 153.132,111.457 152.766,111.452 152.766,112.062
  region net $1N40669: 151.819,104.809 152.219,104.809 152.215,104.747 152.211,104.694 152.212,104.669 152.218,104.645 152.229,104.621 152.248,104.596 151.79,104.596 151.809,104.621 151.82,104.645 151.826,104.669 151.827,104.694 151.823,104.747
  region net $1N40669: 151.819,105.563 152.219,105.563 152.215,105.501 152.211,105.448 152.212,105.423 152.218,105.399 152.229,105.375 152.248,105.35 151.79,105.35 151.809,105.375 151.82,105.399 151.826,105.423 151.827,105.448 151.823,105.501
  region net $1N40669: 152.219,104.733 151.819,104.733 151.823,104.795 151.827,104.848 151.826,104.873 151.82,104.897 151.809,104.921 151.79,104.946 152.248,104.946 152.229,104.921 152.218,104.897 152.212,104.873 152.211,104.848 152.215,104.795
  region net D3/Y-STEP: 114.617,95.924 114.335,95.642 114.294,95.688 114.259,95.729 114.24,95.745 114.219,95.758 114.194,95.768 114.163,95.772 114.487,96.096 114.491,96.065 114.501,96.04 114.514,96.019 114.53,96 114.571,95.965
  region net D3/Y-STEP: 115.33,95.212 115.047,94.929 115.006,94.976 114.971,95.016 114.953,95.033 114.931,95.046 114.906,95.055 114.876,95.06 115.199,95.383 115.204,95.353 115.213,95.328 115.226,95.306 115.243,95.288 115.283,95.253
  region net D3/Y-STEP: 114.46,95.517 114.742,95.799 114.783,95.753 114.818,95.712 114.837,95.696 114.858,95.683 114.883,95.673 114.914,95.669 114.59,95.345 114.586,95.376 114.576,95.401 114.563,95.422 114.547,95.441 114.506,95.476
  region net D2/X-STEP: 121.015,96.611 120.733,96.328 120.692,96.375 120.657,96.416 120.638,96.432 120.617,96.445 120.592,96.454 120.561,96.459 120.885,96.783 120.889,96.752 120.899,96.727 120.912,96.706 120.928,96.687 120.969,96.652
